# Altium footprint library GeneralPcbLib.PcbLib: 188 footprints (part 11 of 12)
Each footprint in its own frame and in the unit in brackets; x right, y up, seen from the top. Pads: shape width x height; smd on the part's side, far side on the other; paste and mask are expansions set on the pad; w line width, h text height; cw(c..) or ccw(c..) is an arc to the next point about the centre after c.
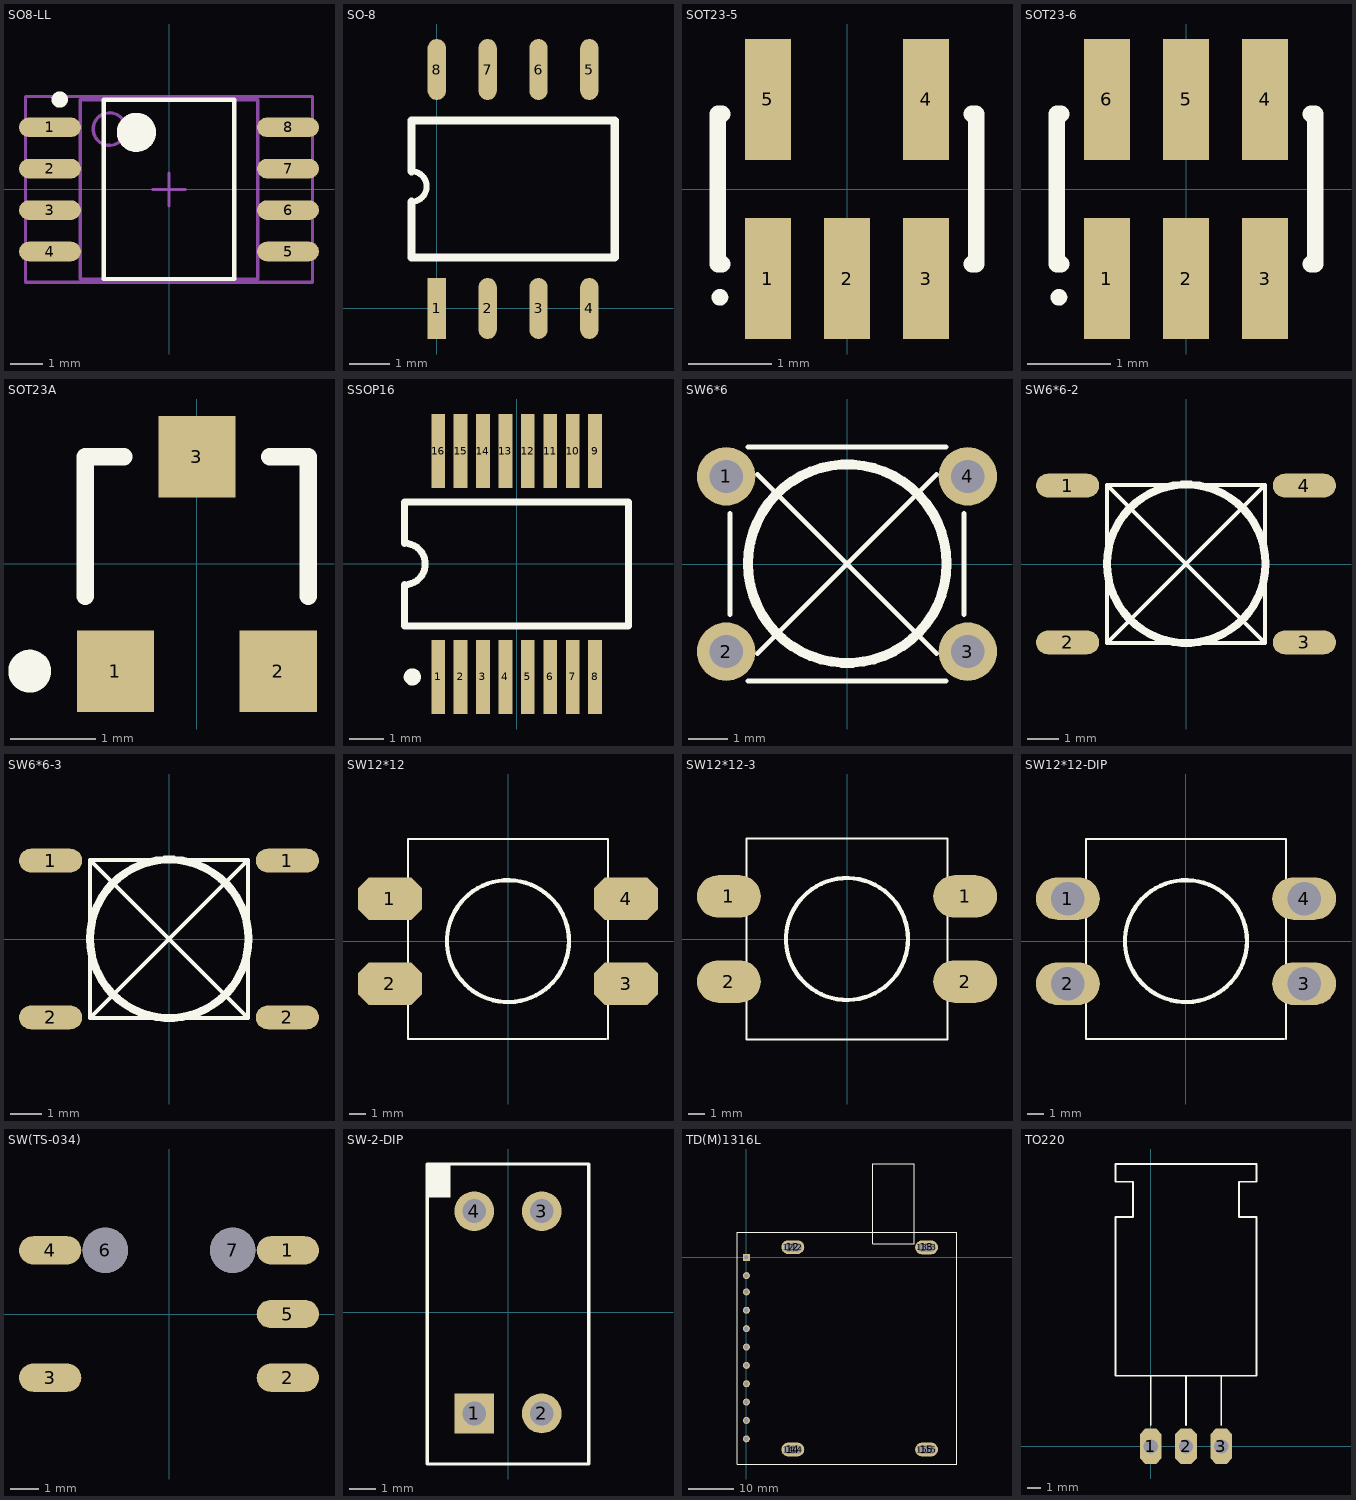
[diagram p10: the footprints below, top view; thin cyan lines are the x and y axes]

## SO8-LL [mm] "S25FL016A"
pads (8):
  oval 1.9x0.6 smd: 1(-3.65,1.905) 2(-3.65,0.635) 3(-3.65,-0.635) 4(-3.65,-1.905) 5(3.65,-1.905) 6(3.65,-0.635) 7(3.65,0.635) 8(3.65,1.905)
Top Overlay:
  circle w0.25: c-3.35,2.755 r0.125
  circle w0.6: c-1,1.75 r0.3
  lines w0.127: -2,-2.75 -2,2.75 2,2.75 2,-2.75 -2,-2.75
Mechanical 13:
  circle w0.1: c-1.825,1.85 r0.5
  lines w0.1: -2.725,-2.75 -2.725,2.75 2.725,2.75 2.725,-2.75 -2.725,-2.75
Mechanical 15:
  lines w0.1: -0.5,0 0.5,0 ; 0,-0.5 0,0.5 ; -4.4,-2.85 -4.4,2.85 4.4,2.85 4.4,-2.85 -4.4,-2.85

## SO-8 [mil]
height 400
pads (8):
  rect 18x60 smd: 1(0.25,0)
  oval 18x60 smd: 2(50.25,0) 3(100.25,0) 4(150.25,0) 5(150.25,235) 6(100.25,235) 7(50.25,235) 8(0.25,235)
Top Overlay:
  lines w6: -24.75,105 ccw(c-24.75,120) -9.75,120 ccw(c-24.75,120) -24.75,135
  lines w8: -24.75,105 -24.75,50 175.25,50 175.25,185 -24.75,185 -24.75,135

## SOT23-5 [mm]
height 1.45
pads (5):
  rect 0.55x1.45 smd: 1(-0.95,-1.075) 2(0,-1.075) 3(0.95,-1.075) 4(0.95,1.075) 5(-0.95,1.075)
Top Overlay:
  circle w0.1: c-1.525,-1.3 r0.05
  lines w0.2: -1.5,-0.9 -1.55,-0.9 -1.55,0.9 -1.5,0.9 ; 1.5,-0.9 1.55,-0.9 1.55,0.9 1.5,0.9

## SOT23-6 [mm] "SOT-23/SC-74A; 5 Leads; Body 3.1 x 3 mm, inc. leads (LxW max)"
height 1.45
pads (6):
  rect 0.55x1.45 smd: 1(-0.95,-1.075) 2(0,-1.075) 3(0.95,-1.075) 4(0.95,1.075) 5(0,1.075) 6(-0.95,1.075)
Top Overlay:
  circle w0.1: c-1.525,-1.3 r0.05
  lines w0.2: -1.5,-0.9 -1.55,-0.9 -1.55,0.9 -1.5,0.9 ; 1.5,-0.9 1.55,-0.9 1.55,0.9 1.5,0.9

## SOT23A [mm] "同：SO-G3/C2.5"
pads (3):
  rect 0.9x0.95 smd: 1(-0.95,-1.25) 2(0.95,-1.25) 3(0,1.25)
Top Overlay:
  circle w0.25: c-1.95,-1.25 r0.125
  lines w0.203: -1.3,-0.375 -1.3,1.25 -0.85,1.25 ; 0.85,1.25 1.3,1.25 1.3,-0.375

## SSOP16 [mm]
pads (16):
  rect 0.4x2.15 smd: 1(-2.275,-3.275) 2(-1.625,-3.275) 3(-0.975,-3.275) 4(-0.325,-3.275) 5(0.325,-3.275) 6(0.975,-3.275) 7(1.625,-3.275) 8(2.275,-3.275) 9(2.275,3.275) 10(1.625,3.275) 11(0.975,3.275) 12(0.325,3.275) 13(-0.325,3.275) 14(-0.975,3.275) 15(-1.625,3.275) 16(-2.275,3.275)
Top Overlay:
  circle w0.25: c-3.025,-3.275 r0.125
  lines w0.2: -3.25,-1.8 -3.25,-0.6 ccw(c-3.25,0) -3.25,0.6 -3.25,1.8 3.25,1.8 3.25,-1.8 -3.25,-1.8

## SW6*6 [mm]
pads (4):
  round 1.5 hole 0.85: 1(-3.1,2.25) 2(-3.1,-2.25) 3(3.1,-2.25) 4(3.1,2.25)
Top Overlay:
  circle w0.254: c0.008,0.008 r2.548
  lines w0.127: -3,-1.3 -3,1.3 ; -2.54,-3 2.54,-3 ; -2.54,3 2.54,3 ; -2.3,-2.3 2.3,2.3 ; -2.3,2.3 2.3,-2.3 ; 3,-1.3 3,1.3

## SW6*6-2 [mil] "FootPrint==1234"
pads (4):
  oval 80x30 smd: 1(-150,99.37) 2(-150,-99.37) 3(150,-99.37) 4(150,99.37)
Top Overlay:
  circle w10: c0.31,0.31 r100.31
  lines w5: -100,-100 100,100 ; -100,-100 -100,100 ; -100,-100 100,-100 ; -100,100 100,-100 ; -100,100 100,100 ; 100,-100 100,100

## SW6*6-3 [mil] "FootPrint=1122"
pads (4):
  oval 80x30 smd: 1(-150,99.37) 1(150,99.37) 2(-150,-99.37) 2(150,-99.37)
Top Overlay:
  circle w10: c0.31,0.31 r100.31
  lines w5: -100,-100 100,-100 ; -100,-100 -100,100 ; -100,-100 100,100 ; -100,100 100,100 ; -100,100 100,-100 ; 100,-100 100,100

## SW12*12 [mil]
pads (4):
  oct 150x100 smd: 1(-277.5,100) 2(-277.5,-100) 3(277.5,-100) 4(277.5,100)
Top Overlay:
  circle w10: c0,0 r143.27
  lines w5: 230,-230 -235,-230 -235,240 235,240 235,-230

## SW12*12-3 [mil]
pads (4):
  oval 150x100 smd: 1(-277.5,100) 1(277.5,100) 2(-277.5,-100) 2(277.5,-100)
Top Overlay:
  circle w10: c0,0 r143.27
  lines w5: -236.22,-236.22 236.22,-236.22 236.22,236.22 -236.22,236.22 -236.22,-236.22

## SW12*12-DIP [mm]
pads (4):
  oval 3.81x2.54 hole 2: 1(-7.048,2.54) 2(-7.048,-2.54) 3(7.048,-2.54) 4(7.049,2.54)
Top Overlay:
  circle w0.254: c0,0 r3.639
  lines w0.127: 5.842,-5.842 -5.969,-5.842 -5.969,6.096 5.969,6.096 5.969,-5.842

## SW(TS-034) [mm]
height 3.4
pads (7):
  oval 2.2x1 smd: 1(4.2,2.25) 2(4.2,-2.25) 3(-4.2,-2.25) 4(-4.2,2.25) 5(4.2,0)
  round 1.6 hole 1.6: 6(-2.25,2.25) 7(2.25,2.25)

## SW-2-DIP [mm] "2位拨码开关"
height 5
pads (4):
  rect 1.5x1.5 hole 0.9: 1(-1.27,-3.81)
  round 1.5 hole 0.9: 2(1.27,-3.81) 3(1.27,3.81) 4(-1.27,3.81)
Top Overlay:
  rectangle: -3.048,4.318 -2.159,5.588
  lines w0.127: -3.048,-5.715 -3.048,5.588 3.048,5.588 3.048,-5.715 -3.048,-5.715

## TD(M)1316L [mil] "高频头"
height 590.55
pads (23):
  rect 60x60 hole 40: 1(0,0)
  round 60 hole 40: 2(0,-157.4) 3(0,-296.83) 4(0,-454.24) 5(0,-611.63) 6(0,-769.03) 7(0,-926.43) 8(0,-1083.84) 9(0,-1240.63) 10(0,-1398.63) 11(0,-1556.04)
  round 118.11 hole 78.74: 12(361,86.5) 12(436,86.5) 13(1507.38,84.61) 13(1582.38,84.61) 14(361,-1647.67) 14(436,-1647.67) 15(1507.38,-1647.67) 15(1582.38,-1647.67)
  oval 196.85x118.11 hole 78.74: 12(397.61,86.5) 13(1544,84.61) 14(397.6,-1647.67) 15(1544,-1647.67)
Top Overlay:
  lines w8: 1081,116.5 1081,799.21 1440,799.21 1440,116.5 1121,116.5 1081,116.5
  lines w10: -79,-1771.5 -79,216.5 1803,216.5 1803,-1771.5 -79,-1771.5

## TO220 [mil] "LM7805"
height 78.74
pads (3):
  oct 62x100 hole 40: 1(0,0) 2(100,0) 3(200,0)
Top Overlay:
  lines w5: 0,60 0,200 ; 100,60 100,200 ; 200,60 200,200 ; -100,200 300,200 300,650 250,650 250,750 300,750 300,800 -100,800 -100,750 -50,750 -50,650 -100,650 -100,200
